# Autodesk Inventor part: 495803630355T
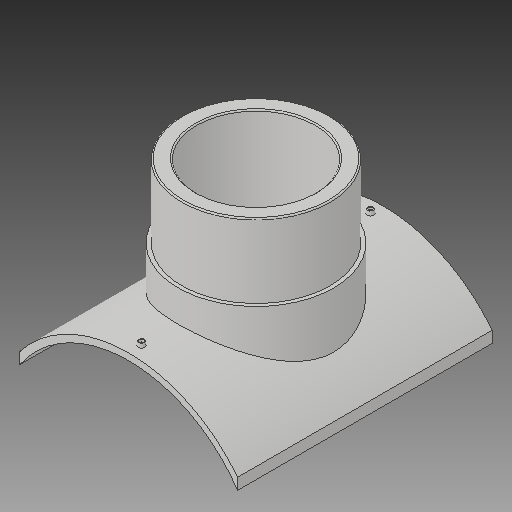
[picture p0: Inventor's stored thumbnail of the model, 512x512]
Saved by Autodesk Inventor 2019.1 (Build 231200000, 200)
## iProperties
Created: 2017-10
Part Number: 495803630355T
Material: Generic
Description: PLASSON BRANCH SADDLE  630x355
Document SubType Name: Modeling
Designer: KIM
Mass: 2754.05 g
Surface Area: 3037.44 cm^2
Volume: 2754.05 cm^3
Density: 1 g/cm^3
Appearance: Default
Author: KIM
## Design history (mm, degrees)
derived "495803.ipt"
feature "Solid1::495803.ipt"
tag "TaggingFeature1"
body "Solid1"
other parameters: "d1" = 16, "d2" = 522, "d4" = 0, "d12" = 340.6, "d13" = 14, "d14" = 274.5, "d16" = 5 deg, "d18" = 4, "d19" = 14, "d20" = 0, "d21" = 3, "d22" = 0, "d23" = 583, "d24" = 372.75, "d25" = 16, "d26" = 284, "d28" = 0, "d29" = 9.6, "d31" = 0, "d32" = 126, "d33" = 0, "d34" = 6.3, "d36" = 355, "d37" = 176.4, "d38" = 0, "d39" = 3.15, "d_1" = 355, "B_" = 522, "H_" = 252, "x_" = 16, "D_" = 16
